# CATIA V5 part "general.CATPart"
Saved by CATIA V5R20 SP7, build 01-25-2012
Part number: squelette_general
Publications: "Point_A", "Point_B", "Point_C", "Point_D", "Point_E", "Point_F", "Point_G", "Plan_Ref", "Plan_Ref_axe", "Longueur_AB", "Diametre", "Largeur", "Epaisseur", "Diametre_pivot"
Bounding box of the stored display mesh (mm): x 0 to 0, y 0 to 702.217, z 0 to 280
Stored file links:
  G:\IAO\apres\general.CATPart
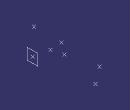
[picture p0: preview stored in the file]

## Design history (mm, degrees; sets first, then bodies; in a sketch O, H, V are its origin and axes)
Parameters
  Longueur_AB = 100 mm
  Diametre = 30 mm
  Largeur = 15 mm
  Epaisseur = 4 mm
  Diametre_pivot = 10 mm
Set1
  Point1 "Point_A": (0, 0, 0), relative to Sketch1.P6
  Point2 "Point_B": (0, 0, 0), relative to Sketch1.P7
  Point3 "Point_C": (0, 0, 0), relative to vertex [element of Sketch1 | element of Sketch1]
  Point4 "Point_D": (0, 0, 0), relative to Sketch1.P4
  Point5 "Point_E": (0, 0, 0), relative to vertex [element of Sketch1 | element of Sketch1]
  Point6 "Point_F": (0, 0, 0), relative to vertex [element of Sketch1 | element of Sketch1]
  Point7 "Point_G": (0, 0, 0), relative to Sketch1.P8
  Plane1 "Plan_Ref": type OffsetPt, RefPlane yz-plane, RefPoint Point7
Body1 (main body)
  Sketch1 on yz-plane, origin (0, 0, 0), H (0, 1, 0), V (0, 0, 1)
    construction circle A1 centre (300, 280) radius 410.3657
    line L1 (188.2401, 155.7819) -> (702.2166, 262.8015)
    point P1 (188.2401, 155.7819)
    point P2 (702.2166, 262.8015)
    point P4 (659.8349, 82.7215)
    line L2 (702.2166, 262.8015) -> (659.8349, 82.7215)
    line L3 (16.1097, 279.5362) -> (188.2401, 155.7819)
    point P5 (188.2401, 155.7819)
    line L4 (300, 280) -> (335.0906, 186.3589)
    point P6 (300, 280)
    point P7 (335.0906, 186.3589)
    line L5 (16.1097, 279.5362) -> (0, 0)
    point P8 (0, 0)
    construction circle A2 centre (0, 0) radius 665
    point P9 (659.8349, 82.7215)
    length L3 = 212 {= 2.12*Longueur_AB}
    length L4 = 100 {= Longueur_AB}
    distance P1 P7 = 150 {= 1.5*Longueur_AB}
    distance P2 P7 = 375 {= 3.75*Longueur_AB}
    length L5 = 280 {= 2.8*Longueur_AB}
    distance P6 P8 H = 300 {= 3*Longueur_AB}
    radius A1 = 410.3657 (reference)
    distance P6 P8 V = 280 {= 2.8*Longueur_AB}
    radius A2 = 665 {= 6.65*Longueur_AB}
    length L2 = 185 {= 1.85*Longueur_AB}
    coincidence: L3 P1, P5 P1, P7 L1, P8 A1, A2 P9, P9 A1, P9 P4, O P8
    concentricity: P6 A1
Relations
  Sketch1.distance(P6 P8 H) = 3*Longueur_AB + (deactivated)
